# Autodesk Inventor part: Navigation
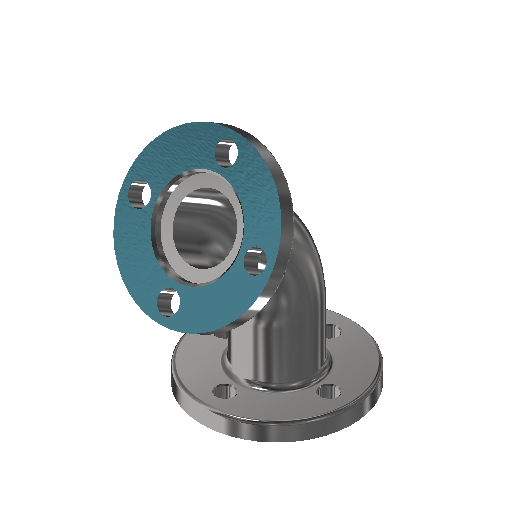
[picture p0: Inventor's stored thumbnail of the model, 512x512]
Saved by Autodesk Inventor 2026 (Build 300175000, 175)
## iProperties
Created: 2013-10
Part Number: Navigation
Material: Stainless Steel, Polished
Document SubType Name: Modeling
Designer: Cadskolen
Density: 8 g/cm^3
Appearance: Stainless - Polished
Author: Cadskolen
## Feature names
1. Extrusion1
2. Revolution1
3. Sweep1
4. Sweep2
5. Extrusion2
6. Hole1
7. Chamfer2
8. Hole2
9. Chamfer4
10. Circular Pattern1
11. Circular Pattern2
12. Fillet1
13. Chamfer3
14. Fillet3
15. Chamfer1
## Parameters: d1 = 15 mm, d2 = 0, d6 = 15 mm, d7 = 90 deg, d9 = 0, d11 = 0, d12 = 65 mm, d13 = 7.5 mm, d14 = 0, d15 = 2 mm, d16 = 4 mm, d17 = 45 deg, d18 = 14 mm, d19 = 6 mm, d20 = 4 mm, d21 = 2 mm, d22 = 90 deg, d23 = 8 mm, d24 = 118 deg, d26 = 360 deg, d28 = 18 mm, d29 = 6 mm, d30 = 4 mm, d31 = 2 mm, d32 = 90 deg, d33 = 8 mm, d34 = 118 deg, d36 = 360 deg, d38 = 5 mm, d40 = 1 mm, d41 = 2 mm, d42 = 45 deg, d43 = 2 mm, d44 = 2 mm, d45 = 45 deg, d46 = 3 mm, d48 = 1 mm, d49 = 2 mm, d50 = 45 deg, d51 = 0, d52 = 0, d53 = 120 deg, d54 = 45 mm
